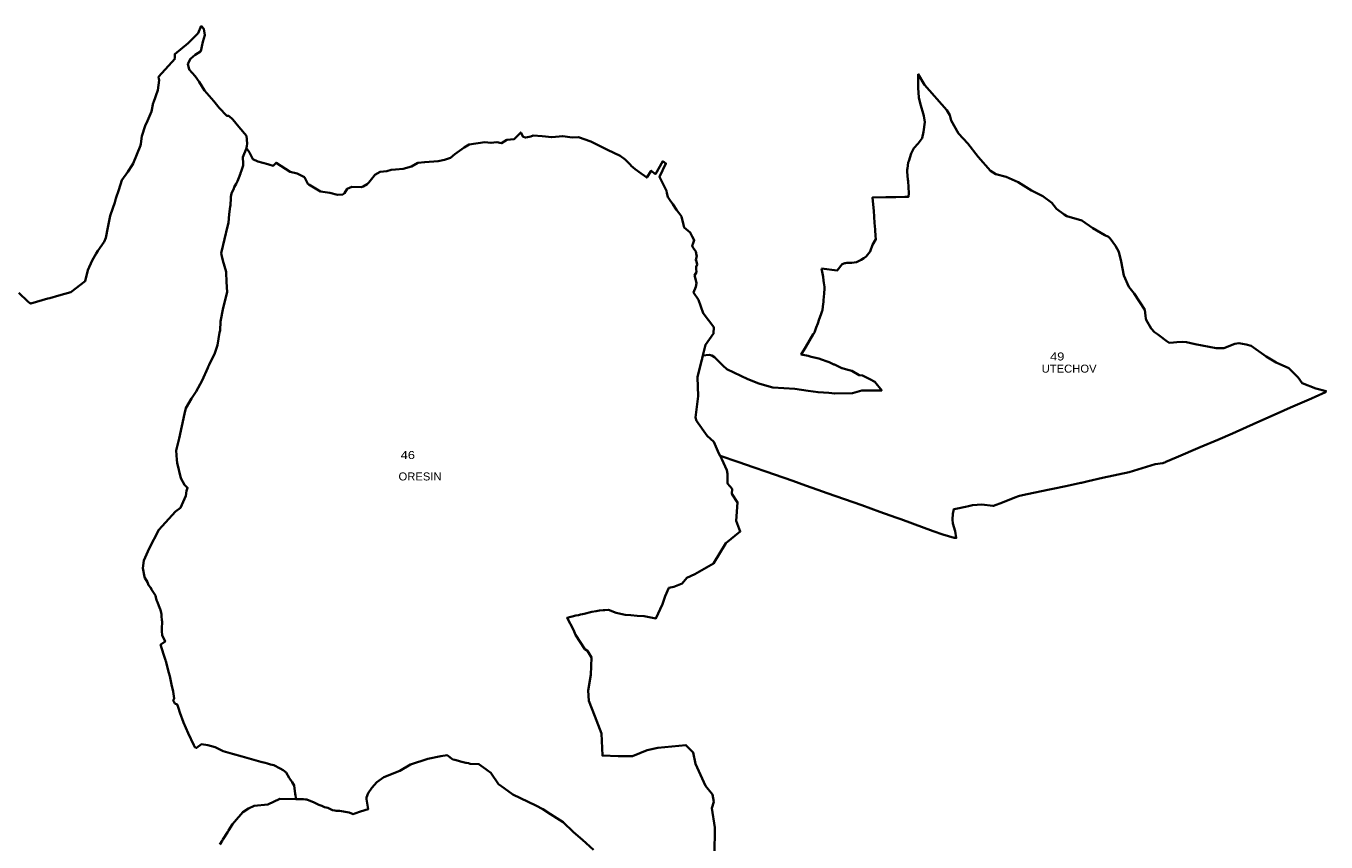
# Model space of a CAD drawing. Extents: x -610940 to -588976, y -1170376 to -1149800.
# Drawn here: x -598167 to -594106, y -1152351 to -1149800 of the extents above; entities that cross this region are included whole.
import ezdxf

# ---------------------------------------------------------------- set-up
doc = ezdxf.new("R2010")
doc.units = 0
doc.header["$LTSCALE"] = 10
doc.layers.add('54', color=7, linetype='Continuous', lineweight=35)
doc.layers.add('55', color=7, linetype='Continuous')
doc.layers.add('56', color=7, linetype='Continuous')

msp = doc.modelspace()

# ---------------------------------------------------------------- linework, layer by layer
at = {"layer": '54'}
for p, q in [((-597629.64, -1149822.37), (-597619.76, -1149799.84)), ((-595359.09, -1150100.08), (-595363.65, -1150130.34)), ((-595367.88, -1150150.81), (-595363.65, -1150130.34)), ((-594753.27, -1150505.92), (-594763.29, -1150487.5)), ((-594745.69, -1150536.32), (-594753.27, -1150505.92)), ((-594737.55, -1150579.79), (-594745.69, -1150536.32)), ((-595681.6, -1150557.94), (-595680.67, -1150563.68)), ((-595672.86, -1150621.44), (-595674.03, -1150635.46)), ((-595672.36, -1150615.43), (-595672.86, -1150621.44)), ((-595674.03, -1150635.46), (-595675.03, -1150647.49)), ((-595684.38, -1150703.24), (-595689.16, -1150716.39)), ((-595679.61, -1150690.1), (-595684.38, -1150703.24)), ((-595678.93, -1150688.22), (-595679.61, -1150690.1)), ((-595689.16, -1150716.39), (-595693.93, -1150729.53)), ((-596052.75, -1150830.56), (-596053.01, -1150831.62)), ((-596033.18, -1150828.03), (-596052.75, -1150830.56)), ((-596054.61, -1150838.2), (-596055.08, -1150840.15)), ((-596053.01, -1150831.62), (-596054.61, -1150838.2)), ((-595989.93, -1150861.02), (-596016.42, -1150834.94)), ((-595852.42, -1150925.13), (-595877.89, -1150917.49)), ((-594871.79, -1151228.11), (-594869.82, -1151227.69)), ((-595075.27, -1151272.9), (-595088.17, -1151277.99))]:
    msp.add_line(p, q, dxfattribs=at)
for points in [[(-597619.76, -1149799.84), (-597611.28, -1149809.01), (-597608.36, -1149828.96), (-597614.56, -1149849.74), (-597617.38, -1149863.48), (-597620.19, -1149874.94), (-597621.45, -1149879.59), (-597638.2, -1149890.3), (-597653.31, -1149902.46), (-597661.16, -1149917.83), (-597657.44, -1149935.76), (-597638.69, -1149957.17), (-597626.25, -1149974.25), (-597609.17, -1150001.08), (-597580.37, -1150035.24), (-597563.65, -1150055.97), (-597539.54, -1150081.13), (-597533.71, -1150081.08), (-597521.15, -1150091.81), (-597501.79, -1150115.25), (-597478.11, -1150143.39), (-597476.42, -1150167.47), (-597477.73, -1150175.35), (-597478.26, -1150179.37), (-597478.57, -1150182.25), (-597489.41, -1150210.36), (-597488.66, -1150229.64), (-597488.57, -1150232.01), (-597488.51, -1150233.75), (-597488.41, -1150236.25), (-597489.49, -1150239.46), (-597493.57, -1150251.65), (-597496.75, -1150260.51), (-597496.85, -1150260.8), (-597501.71, -1150274.35), (-597506.65, -1150284.54), (-597510.78, -1150293.08), (-597516.28, -1150303.8), (-597518.03, -1150307.55), (-597525.35, -1150323.19)], [(-598092.42, -1150650.33), (-598064.1, -1150642.55), (-598027.21, -1150631.99), (-597982.56, -1150597.41), (-597974.4, -1150563.41), (-597960.13, -1150532.67), (-597947.57, -1150511.17), (-597942.88, -1150503.31), (-597922.81, -1150474.33), (-597917.21, -1150461.78), (-597911.37, -1150430.02), (-597904.43, -1150393.47), (-597903.08, -1150390.31), (-597889.84, -1150351.56), (-597886.38, -1150338.89), (-597877.49, -1150312.2), (-597867.93, -1150281.86), (-597848.53, -1150255.94), (-597835.14, -1150235.18), (-597831.82, -1150229.29), (-597809.56, -1150173.45), (-597808.41, -1150168.37), (-597804.97, -1150144.66), (-597794.45, -1150112.45), (-597787.15, -1150095.98), (-597775.06, -1150067.71), (-597769.74, -1150040.47), (-597769.27, -1150038.68), (-597755.2, -1150000.97), (-597751.44, -1149969.17), (-597752.08, -1149965.07), (-597752.79, -1149958.84), (-597701.5, -1149901.64), (-597701.65, -1149899.98), (-597701.76, -1149898.62), (-597702.17, -1149891.29), (-597702.27, -1149890.8), (-597702.17, -1149887.8), (-597660.71, -1149853.37), (-597629.64, -1149822.37)], [(-595359.09, -1150100.08), (-595362.22, -1150080.65), (-595373.86, -1150041.3), (-595377.55, -1150023.57), (-595379.95, -1149993.19), (-595380.17, -1149957.69), (-595380.02, -1149950.92), (-595360.29, -1149983.68), (-595290.58, -1150063.32), (-595281.28, -1150078.32), (-595277.16, -1150094.93), (-595254.1, -1150136.32), (-595225.44, -1150167.22), (-595192.99, -1150209.28), (-595154.54, -1150253.02), (-595137.06, -1150263.25), (-595104.74, -1150271.1), (-595068.19, -1150288.05), (-595026.14, -1150314.13), (-594990.6, -1150331.57), (-594962.06, -1150353.14), (-594948.35, -1150371.04), (-594923.64, -1150388.79), (-594915.41, -1150394.71), (-594868.41, -1150407.93), (-594834.87, -1150432.16), (-594796.49, -1150453.38), (-594785.94, -1150459.53), (-594780.33, -1150464.61), (-594763.29, -1150487.5)], [(-596827.41, -1150200.68), (-596798.79, -1150179.85), (-596782.88, -1150170.12), (-596733.4, -1150163.32), (-596714.77, -1150165.58), (-596695.88, -1150163.05), (-596681.98, -1150166.6), (-596665.17, -1150156.09), (-596642.09, -1150153.71), (-596621.5, -1150132.5), (-596614.42, -1150145.96), (-596606.63, -1150148.87), (-596600.21, -1150147.29), (-596590.51, -1150144.87), (-596582.51, -1150141.83), (-596554.39, -1150144.64), (-596524.51, -1150147.66), (-596490.47, -1150144.19), (-596460.48, -1150148.72), (-596441.29, -1150147.65), (-596402.98, -1150161.14), (-596350.6, -1150186.81), (-596310.5, -1150205.96), (-596295.34, -1150217.5), (-596278.89, -1150234.37), (-596276.26, -1150236.99), (-596264.29, -1150247.02), (-596256.73, -1150252.45), (-596252.23, -1150255.78), (-596227.91, -1150273.91), (-596214.11, -1150252.5), (-596200.69, -1150262.8), (-596178.14, -1150222.78), (-596168.14, -1150229.27), (-596187.78, -1150271.44), (-596177.12, -1150294.1), (-596166.33, -1150315.72), (-596164.92, -1150321.59), (-596161.59, -1150334.92), (-596161.09, -1150336.47)], [(-595410.87, -1150226.85), (-595409.5, -1150222.46), (-595402.13, -1150198.89), (-595393.22, -1150181.89), (-595379.98, -1150167.66), (-595367.88, -1150150.81)], [(-597478.57, -1150182.25), (-597468.7, -1150195.68), (-597458.86, -1150215.8), (-597442.84, -1150223.17), (-597412.12, -1150231.36), (-597404.9, -1150233.92), (-597397.98, -1150235.98), (-597394.46, -1150237), (-597385.92, -1150227.38), (-597341.56, -1150256.04), (-597319.74, -1150261.28), (-597297.26, -1150272.94), (-597286.71, -1150293.05), (-597283.64, -1150295.25), (-597278.62, -1150298.14), (-597247.04, -1150317.76), (-597217.42, -1150321.16), (-597193.79, -1150327.31), (-597177.66, -1150326.96), (-597172.11, -1150322.43), (-597163.49, -1150308.52), (-597149.08, -1150303.17), (-597119.94, -1150303.72), (-597113.98, -1150301.22), (-597101.18, -1150294.68), (-597096.39, -1150289.07), (-597079.05, -1150267.95), (-597076.96, -1150265.36), (-597060.67, -1150255.78), (-597039.6, -1150253.66), (-597026.63, -1150249.9), (-597012.43, -1150248.58), (-596988.59, -1150246.56), (-596963.23, -1150238.79), (-596943.26, -1150228.02), (-596921.26, -1150225.22), (-596879.05, -1150222.52), (-596860.05, -1150217.89), (-596841.51, -1150211.6), (-596827.41, -1150200.68)], [(-595414.84, -1150255.9), (-595412.21, -1150279.3), (-595411.82, -1150285.43), (-595409.38, -1150322.69), (-595410.43, -1150334.1), (-595413.05, -1150334.14), (-595419.16, -1150334.24), (-595422.12, -1150334.29), (-595449.97, -1150334.75), (-595480.64, -1150335.25), (-595522.3, -1150335.95), (-595520.52, -1150358.42), (-595518.95, -1150378.14), (-595517.53, -1150396.08), (-595516.03, -1150415.76), (-595514.48, -1150435.76), (-595514.2, -1150438.53), (-595512.93, -1150455.76), (-595512.25, -1150466.51), (-595522.38, -1150483.56), (-595529.58, -1150505.09), (-595542.18, -1150520.19), (-595549.62, -1150526.25), (-595558.39, -1150531.2), (-595560.38, -1150532.28), (-595573.11, -1150538.25), (-595579.89, -1150538.92), (-595587.66, -1150539.93), (-595602.53, -1150540.49), (-595607.26, -1150541.16), (-595608.87, -1150541.71), (-595617.65, -1150544.69), (-595633.02, -1150564.08), (-595681.6, -1150557.94)], [(-595410.87, -1150226.85), (-595413.77, -1150245.7), (-595414.23, -1150248.64), (-595414.84, -1150255.9)], [(-597525.35, -1150323.19), (-597526.73, -1150333.96), (-597527.16, -1150337.26), (-597528.7, -1150361.58), (-597529.49, -1150364.14), (-597532.01, -1150388.24), (-597534.81, -1150414.87), (-597537.64, -1150426.42), (-597556.65, -1150506.21), (-597557.64, -1150510.4), (-597556.48, -1150515.72), (-597555.71, -1150519.22), (-597552.61, -1150533.42), (-597541.46, -1150568.89), (-597541.4, -1150570.36), (-597540.23, -1150599.78), (-597538.41, -1150632.54), (-597551.61, -1150681.26), (-597559.85, -1150723.74), (-597560.71, -1150751.86), (-597562.51, -1150758.32), (-597569.26, -1150797.62), (-597578.42, -1150825.98), (-597590.07, -1150848.24), (-597595.02, -1150859.38), (-597597.95, -1150865.65), (-597599.11, -1150868.14), (-597616.59, -1150908.18), (-597635.14, -1150942.82), (-597650.25, -1150964.09), (-597667.95, -1150994.24), (-597672.28, -1151012.95), (-597689.11, -1151090.03), (-597698.37, -1151127.37), (-597695.56, -1151156.58), (-597694.64, -1151166.11), (-597683.19, -1151214.08), (-597671.96, -1151234.15), (-597662.17, -1151243.63), (-597666.17, -1151253.28)], [(-596161.09, -1150336.47), (-596154.76, -1150345.76), (-596146.93, -1150356.92), (-596134.77, -1150374.25), (-596127.6, -1150383.92), (-596121.77, -1150392.58), (-596119.36, -1150395.95), (-596112.95, -1150421.24), (-596110.58, -1150429.45), (-596091.96, -1150445.94), (-596085.63, -1150458.23), (-596079.67, -1150469.86), (-596082.63, -1150478.56), (-596086.47, -1150487.56), (-596082.8, -1150493.4), (-596075.14, -1150505.27), (-596072.31, -1150516.72), (-596071.6, -1150519.35), (-596074.77, -1150530.81), (-596072.98, -1150536.39), (-596070.2, -1150545.72), (-596073.57, -1150553.3), (-596073.16, -1150559.22), (-596072.49, -1150569.09), (-596078.7, -1150580.09), (-596077, -1150586.38), (-596072.09, -1150603.96), (-596074.42, -1150615.58), (-596081.59, -1150633.5), (-596066.68, -1150656.16), (-596051.86, -1150697.82), (-596018.63, -1150741.1), (-596019.13, -1150761.73), (-596044.39, -1150796.56), (-596052.75, -1150830.56)], [(-595680.67, -1150563.68), (-595677.31, -1150584.41), (-595675.53, -1150595.38)], [(-594139.58, -1150958.93), (-594107.95, -1150945), (-594106.11, -1150941.43), (-594137.65, -1150932.92), (-594180.72, -1150916.11), (-594192.57, -1150898.8), (-594222.72, -1150869.61), (-594262.3, -1150851.99), (-594292.84, -1150832.85), (-594340.22, -1150800.17), (-594355.38, -1150796.1), (-594378.12, -1150791.95), (-594391.1, -1150793.57), (-594425.24, -1150806.73), (-594449.66, -1150807.63), (-594515.16, -1150794.49), (-594542.19, -1150788.21), (-594554.54, -1150787.34), (-594572.55, -1150788.73), (-594582.43, -1150789.5), (-594595.79, -1150790.53), (-594605.93, -1150783.11), (-594623.66, -1150770.13), (-594632.43, -1150763.71), (-594641.33, -1150757.24), (-594652.32, -1150745.26), (-594668.37, -1150718.44), (-594668.85, -1150713.95), (-594669.66, -1150706.28), (-594671.67, -1150687.44), (-594705.31, -1150636.07), (-594721.92, -1150615.07), (-594737.55, -1150579.79)], [(-595675.53, -1150595.38), (-595674.3, -1150603.17), (-595672.36, -1150615.43)], [(-598189.4, -1150633.85), (-598161.82, -1150660.72), (-598155.72, -1150664.98), (-598151.86, -1150667.65), (-598099.33, -1150652.2), (-598092.42, -1150650.33)], [(-595676.22, -1150661.84), (-595677.71, -1150676.37), (-595678.93, -1150688.22)], [(-595675.03, -1150647.49), (-595675.78, -1150656.5), (-595676.22, -1150661.84)], [(-595693.93, -1150729.53), (-595698.7, -1150742.68), (-595704.16, -1150757.71)], [(-595704.16, -1150757.71), (-595706.07, -1150760.89), (-595707.61, -1150763.46), (-595719.55, -1150783.32), (-595731.31, -1150802.9), (-595745.48, -1150826.48), (-595724.09, -1150831.37), (-595713.87, -1150833.72), (-595690.25, -1150839.14), (-595681.88, -1150842.45), (-595664.34, -1150848.59), (-595658.07, -1150850.78), (-595643.3, -1150857.68), (-595641.7, -1150858.43), (-595618.44, -1150869.3), (-595617.68, -1150869.65), (-595599.9, -1150874.7), (-595587.38, -1150878.25), (-595564.45, -1150891.75), (-595554.41, -1150892.38), (-595530.95, -1150904.47), (-595515.86, -1150912.24), (-595494.07, -1150939.15), (-595536.68, -1150939.09), (-595555.94, -1150939.06), (-595585.75, -1150947.42), (-595640.91, -1150949.37), (-595659.12, -1150947.01), (-595692.76, -1150944.94), (-595723.25, -1150940.49), (-595765.02, -1150934.31), (-595834.53, -1150930.5), (-595852.42, -1150925.13)], [(-596016.42, -1150834.94), (-596024.46, -1150830.04), (-596033.18, -1150828.03)], [(-596056.67, -1150846.69), (-596069.03, -1150897.51), (-596067.55, -1150957)], [(-596055.08, -1150840.15), (-596055.9, -1150843.54), (-596056.67, -1150846.69)], [(-595877.89, -1150917.49), (-595912.59, -1150903.97), (-595977.85, -1150872.92), (-595989.93, -1150861.02)], [(-596072.78, -1151034.44), (-596075.78, -1151023.69), (-596067.55, -1150957)], [(-594259.02, -1151011.28), (-594217.28, -1150992.13), (-594151.5, -1150964.14)], [(-594151.5, -1150964.14), (-594149.22, -1150963.17), (-594147.32, -1150962.33), (-594141.81, -1150959.91), (-594139.58, -1150958.93)], [(-594869.82, -1151227.69), (-594849.34, -1151222.58), (-594804.32, -1151212.59), (-594721.41, -1151194.77), (-594639.35, -1151169.68), (-594616.31, -1151167), (-594614.04, -1151165.88), (-594609.98, -1151164.12), (-594606.82, -1151162.61), (-594574.63, -1151148.87), (-594498.77, -1151116.61), (-594443.7, -1151093.41), (-594397.93, -1151073.62), (-594322.54, -1151039.37), (-594259.02, -1151011.28)], [(-595088.17, -1151277.99), (-595116.52, -1151289.17), (-595144.83, -1151300.34), (-595147.3, -1151300.05), (-595181.43, -1151296.01), (-595195.29, -1151297.14), (-595210.56, -1151298.22), (-595222.95, -1151301.34), (-595231.91, -1151303.64), (-595257.02, -1151307.97), (-595262.66, -1151309.25), (-595266.79, -1151310.16), (-595268.98, -1151310.65), (-595272.12, -1151325.53), (-595272.84, -1151343.11), (-595271.58, -1151355.52), (-595264.22, -1151379.75), (-595260.98, -1151400.52), (-595264.59, -1151400.32), (-595267.97, -1151400.14), (-595303.41, -1151389.45), (-595333.16, -1151379.46), (-595398.24, -1151355.1), (-595433.83, -1151341.97), (-595450, -1151336.72), (-595499.36, -1151318.86), (-595555.72, -1151298.34), (-595663.97, -1151260.1), (-595693.28, -1151249.66), (-595731.98, -1151236.72), (-595772.11, -1151222.41), (-595829.12, -1151202.42), (-595856.25, -1151192.99), (-595892.04, -1151180.54), (-595943.94, -1151162.73), (-595998.85, -1151144.25), (-596002.4, -1151136.53), (-596018.46, -1151099.66), (-596038.95, -1151081.68), (-596072.78, -1151034.44)], [(-595998.85, -1151144.25), (-595993.82, -1151154.01), (-595978.04, -1151188.06), (-595976.21, -1151200.14), (-595975.43, -1151230.35), (-595961.15, -1151247.23), (-595961.65, -1151263.02), (-595943.95, -1151289.57), (-595948.97, -1151346.86), (-595935.73, -1151380.44), (-595980.87, -1151417.18), (-596019.22, -1151479.84), (-596078.09, -1151513.91), (-596102.72, -1151525.53), (-596117.43, -1151543.03), (-596143.81, -1151553.23), (-596158.68, -1151556.85), (-596170.27, -1151581.97), (-596178.7, -1151607.93), (-596199.08, -1151652.09), (-596236.29, -1151645.29), (-596257.57, -1151643.62), (-596277.2, -1151642.24), (-596295.65, -1151640.69), (-596323.11, -1151634.39), (-596347.35, -1151625.1), (-596358.89, -1151626.05), (-596364.27, -1151626.51), (-596375.76, -1151627.5), (-596385.93, -1151629.09), (-596399.14, -1151631.96), (-596423.97, -1151637.7), (-596428.3, -1151638.7), (-596435.18, -1151640.24), (-596440.89, -1151641.45), (-596449.34, -1151643.4), (-596476.72, -1151650.23), (-596457.02, -1151687.74), (-596450.32, -1151703.78), (-596421.46, -1151748.37)], [(-594969.78, -1151248.8), (-594959.23, -1151246.42), (-594919, -1151238.25), (-594871.79, -1151228.11)], [(-597666.17, -1151253.28), (-597667.74, -1151269.02), (-597684.7, -1151305.93), (-597700.24, -1151317.96), (-597752.44, -1151375.24), (-597782.33, -1151433.64), (-597786.9, -1151442.57), (-597799.42, -1151471.04), (-597802.49, -1151494.73), (-597797.29, -1151521.73), (-597795.49, -1151525.55), (-597787.28, -1151539.01), (-597783.94, -1151548.55), (-597776.97, -1151555.97), (-597775.24, -1151561.87), (-597768.37, -1151570.91), (-597762.9, -1151580.84), (-597760.28, -1151591.22), (-597759.49, -1151594.32), (-597759.12, -1151595.09), (-597755.93, -1151601.71), (-597752, -1151612.35), (-597748.08, -1151622.98), (-597747.22, -1151625.23), (-597745, -1151634.89), (-597744.22, -1151638.81), (-597743.39, -1151643.65), (-597742.24, -1151658.5), (-597742.13, -1151660.54), (-597742.45, -1151686), (-597742.52, -1151692.3), (-597742.12, -1151704.55), (-597732.45, -1151724.28), (-597745.52, -1151733.21), (-597746.72, -1151734.03), (-597737.17, -1151763.98), (-597731.2, -1151782.15), (-597730.73, -1151783.58), (-597729.93, -1151785.18), (-597720.93, -1151821.69)], [(-594969.78, -1151248.8), (-595039.61, -1151263.07), (-595063.64, -1151268.3), (-595070.07, -1151270.84), (-595075.27, -1151272.9)], [(-596421.46, -1151748.37), (-596413.3, -1151752.87), (-596400.77, -1151773.79), (-596402.7, -1151828.46), (-596410.47, -1151877.17), (-596408.56, -1151909.29), (-596390.54, -1151957.59), (-596368.89, -1152011.6), (-596366.62, -1152080.8), (-596317.71, -1152083.07), (-596272.55, -1152082.66), (-596226.88, -1152063.67), (-596193, -1152056.47), (-596105.84, -1152048.12), (-596082.44, -1152071.21), (-596075.53, -1152106.67), (-596044.31, -1152175.18), (-596022.78, -1152202.18), (-596018.33, -1152225.73), (-596025.12, -1152245.02), (-596015.77, -1152305.6), (-596016.42, -1152391.27)], [(-597720.93, -1151821.69), (-597718.13, -1151833.05), (-597712.22, -1151858.88), (-597707.23, -1151880.96), (-597703.71, -1151902.91), (-597707.15, -1151908.97), (-597705.67, -1151911.46), (-597703.2, -1151915.57), (-597701.85, -1151917.83), (-597694.56, -1151921), (-597693.64, -1151923.69), (-597690.65, -1151932.66), (-597686.09, -1151945.75), (-597674.98, -1151977.6), (-597674.99, -1151977.7), (-597660.74, -1152010.46), (-597642.6, -1152048.82), (-597639.71, -1152054.55), (-597634.1, -1152056.66), (-597619.2, -1152045.4), (-597598.82, -1152047.8), (-597575.77, -1152054.76), (-597550.9, -1152067.57), (-597522.13, -1152075.46), (-597491.5, -1152084.14), (-597433.37, -1152100.7), (-597419.51, -1152103.23), (-597413.07, -1152105.49), (-597403.58, -1152108.86), (-597393.11, -1152111.06), (-597373.38, -1152121.47), (-597363.26, -1152126.6), (-597354.48, -1152133.45), (-597344.58, -1152150.58), (-597335.9, -1152164.07), (-597332.92, -1152168.69), (-597329.26, -1152174.37), (-597325.94, -1152200.97), (-597325.36, -1152205.65), (-597324.5, -1152212.26)], [(-596552.05, -1152248.35), (-596574.81, -1152237.17), (-596622.01, -1152214.2), (-596646.75, -1152202.1), (-596673.34, -1152183.02), (-596690.68, -1152170.66), (-596715.34, -1152134.34), (-596726.06, -1152126.59), (-596731.06, -1152123.01), (-596752.44, -1152107.55), (-596780.08, -1152106.25), (-596785.18, -1152104.82), (-596792, -1152103.21), (-596793.04, -1152103.07), (-596809.87, -1152098.99), (-596816.32, -1152097.27), (-596827.1, -1152094.62), (-596833.46, -1152093.04), (-596851.5, -1152079.52), (-596871.27, -1152083.01), (-596911.33, -1152090.85), (-596966.24, -1152109.16), (-596999.63, -1152128.73), (-597049.75, -1152148.13), (-597070.81, -1152163.85), (-597086.78, -1152181.31), (-597098.54, -1152197.91), (-597103.82, -1152211.42), (-597102.9, -1152217.24), (-597097.93, -1152248.14), (-597122.37, -1152256.09), (-597139.76, -1152262.25), (-597144.77, -1152264.02), (-597157.9, -1152259.3), (-597187.29, -1152253.83), (-597197.89, -1152253.2), (-597202.03, -1152252.49), (-597209.29, -1152251.38), (-597224.25, -1152244.05), (-597234.12, -1152242.65)], [(-597324.5, -1152212.26), (-597324.43, -1152213.09), (-597323.96, -1152216.84), (-597373.68, -1152216.25), (-597412.03, -1152234), (-597454.24, -1152237.48), (-597472.19, -1152246.38), (-597489.33, -1152257.55), (-597516.23, -1152288.35), (-597522.43, -1152295.33), (-597534.97, -1152315.6), (-597537.07, -1152318.98), (-597552.36, -1152343.69), (-597554.46, -1152347.09), (-597561.53, -1152358.53)], [(-597234.12, -1152242.65), (-597241.24, -1152239.38), (-597241.71, -1152239.31), (-597243.33, -1152238.42), (-597251.85, -1152234.51), (-597266.74, -1152227.8), (-597290.23, -1152218.08), (-597293.84, -1152217.79), (-597300.52, -1152217.44), (-597323.96, -1152216.84)], [(-596394.58, -1152375.26), (-596428.18, -1152343.88), (-596456.94, -1152320.21), (-596489.37, -1152289.2), (-596528.28, -1152264.22), (-596552.05, -1152248.35)]]:
    msp.add_lwpolyline(points, dxfattribs=at)

# ---------------------------------------------------------------- texts
at = {"layer": '55', "width": 1.05}
for s, p in [('UTECHOV ', (-594994.37, -1150883.63)), ('ORESIN ', (-597003.37, -1151220.68))]:
    msp.add_text(s, height=25, dxfattribs=at).set_placement(p)
at = {"layer": '56', "width": 1.2}
for s, p in [('49 ', (-594968.13, -1150845.57)), ('46 ', (-596996.65, -1151153.73))]:
    msp.add_text(s, height=25, dxfattribs=at).set_placement(p)

doc.saveas('drawing.dxf')
